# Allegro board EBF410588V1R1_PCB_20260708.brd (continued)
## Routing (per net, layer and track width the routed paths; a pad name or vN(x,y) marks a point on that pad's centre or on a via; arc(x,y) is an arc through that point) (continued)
HDMI_TX_D2N_PORT: length 21.8
  TOP w0.084: J33.3 98.59,80.48 arc(98.56,80.62) 98.48,80.74 98.41,80.81 arc(98.27,80.91) 98.1,80.94 98,80.94 arc(97.91,80.92) 97.84,80.88 97.69,80.72 arc(97.54,80.5) 97.49,80.23 97.49,78.89 arc(97.35,78.19) 96.95,77.6 94.2,74.84 arc(94.04,74.6) 93.98,74.32 93.98,68.65 arc(93.9,68.23) 93.66,67.88 93.1,67.32 arc(92.98,67.24) 92.84,67.21 92.48,67.21 arc(92.41,67.2) 92.36,67.16 91.91,66.71 arc(91.87,66.65) 91.86,66.58 91.86,66.34 arc(91.86,66.31) 91.88,66.28 91.96,66.2 arc(92.03,66.1) 92.05,65.97 D54.2 91.87,65.6 91.87,64.92 arc(91.88,64.86) 91.92,64.81 R229.1 91.85,64.16 arc(91.81,64.09) 91.79,64.01 91.79,63.99 arc(91.81,63.91) 91.85,63.84 C217.2
HDMI_TX_D2P: length 82
  TOP w0.084: CN2.69 65.92,45.48 arc(65.91,45.42) 65.88,45.37 65.87,45.36 arc(65.83,45.31) 65.82,45.25 65.82,44.28 arc(65.83,44.22) 65.87,44.17 v1(65.92,44.11) ; v1(91.22,59.43) 91.37,59.43 arc(91.41,59.44) 91.43,59.46 91.44,59.46 arc(91.55,59.63) 91.59,59.84 91.59,62.05 arc(91.59,62.08) 91.57,62.11 C216.1
  BOTTOM w0.084: v1(65.92,44.11) 65.92,43.92 arc(65.89,43.76) 65.8,43.63 65.53,43.35 arc(65.46,43.25) 65.43,43.12 65.43,42.97 65.44,42.96 65.44,42.8 arc(65.48,42.6) 65.59,42.43 66.06,41.96 arc(66.09,41.92) 66.1,41.87 66.1,40.55 arc(66.14,40.35) 66.25,40.17 67.38,39.05 arc(67.75,38.8) 68.18,38.71 74.21,38.71 arc(74.78,38.6) 75.26,38.28 75.45,38.09 arc(75.99,37.72) 76.63,37.6 97.28,37.6 arc(97.92,37.72) 98.46,38.09 105.09,44.71 arc(105.46,45.26) 105.58,45.9 105.58,53.87 arc(105.46,54.51) 105.09,55.06 104.59,55.55 arc(104.27,56.03) 104.16,56.6 104.16,56.99 arc(104.03,57.64) 103.67,58.18 103.53,58.32 arc(103.21,58.8) 103.09,59.37 103.09,59.69 arc(102.83,60.33) 102.18,60.6 99.06,60.6 arc(98.42,60.47) 97.88,60.11 97.77,60 arc(97.29,59.68) 96.72,59.56 93.68,59.56 arc(93.61,59.58) 93.54,59.62 93.14,60.02 arc(92.75,60.28) 92.29,60.38 91.97,60.38 arc(91.78,60.34) 91.63,60.23 91.61,60.22 arc(91.5,60.06) 91.47,59.87 91.47,59.84 arc(91.44,59.69) 91.35,59.56 v1(91.22,59.43)
HDMI_TX_D2P_PORT: length 21.8
  TOP w0.084: J33.1 98.41,81.29 arc(98.25,81.18) 98.05,81.14 98,81.14 arc(97.84,81.11) 97.7,81.02 97.55,80.86 arc(97.36,80.57) 97.29,80.23 97.29,78.89 arc(97.16,78.26) 96.81,77.74 94.06,74.98 arc(93.85,74.68) 93.78,74.32 93.78,68.65 arc(93.71,68.31) 93.52,68.02 92.96,67.46 arc(92.9,67.42) 92.84,67.41 92.48,67.41 arc(92.34,67.38) 92.22,67.3 91.77,66.85 arc(91.69,66.73) 91.66,66.58 91.66,66.34 arc(91.65,66.31) 91.63,66.28 91.55,66.2 arc(91.49,66.1) 91.46,65.97 D53.2 91.57,65.68 arc(91.64,65.57) 91.67,65.44 91.67,65.28 arc(91.62,65.03) 91.47,64.81 R230.1 91.53,64.17 arc(91.58,64.09) 91.59,64.01 91.59,63.99 arc(91.58,63.91) 91.53,63.83 C216.2
HDMI_TX_D3N: length 74.5
  TOP w0.084: v1(66.92,43.11) 66.92,43.3 arc(66.89,43.45) 66.8,43.59 66.63,43.75 arc(66.48,43.99) 66.42,44.26 66.42,45.25 arc(66.41,45.31) 66.38,45.36 66.37,45.37 arc(66.33,45.42) 66.32,45.48 CN2.71 ; v1(101.26,59.43) 101.38,59.43 arc(101.46,59.45) 101.53,59.49 101.54,59.5 arc(101.59,59.57) 101.6,59.65 101.6,60.1 arc(101.54,60.25) 101.39,60.31 101.22,60.31 arc(100.93,60.43) 100.81,60.72 100.81,60.73 arc(100.93,61.01) 101.21,61.13 101.39,61.13 arc(101.54,61.19) 101.6,61.34 101.6,61.94 arc(101.57,62.1) 101.48,62.23 C223.1
  BOTTOM w0.084: v1(101.26,59.43) 101.44,59.43 arc(101.55,59.41) 101.64,59.35 101.65,59.34 arc(101.71,59.25) 101.73,59.14 101.73,59.06 arc(101.71,58.94) 101.64,58.84 101.52,58.72 arc(101.37,58.5) 101.32,58.24 101.32,57.86 arc(101.44,57.57) 101.73,57.45 102.84,57.45 arc(103.05,57.24) 102.84,57.03 100.58,57.03 arc(100.23,56.88) 100.08,56.53 100.08,56.39 arc(100.19,56.12) 100.46,56.01 102.03,56.01 arc(102.24,55.8) 102.03,55.59 101.83,55.59 arc(101.47,55.44) 101.32,55.08 101.32,54.97 arc(101.45,54.67) 101.74,54.55 102.85,54.55 arc(103.42,54.43) 103.9,54.11 103.96,54.05 arc(104.28,53.57) 104.39,53.01 104.39,46.42 arc(104.28,45.85) 103.96,45.37 97.67,39.09 arc(97.2,38.77) 96.63,38.65 78.19,38.65 arc(77.62,38.77) 77.14,39.09 76.7,39.53 arc(76.15,39.9) 75.51,40.03 68.27,40.03 arc(68.02,40.07) 67.81,40.21 67.67,40.36 arc(67.64,40.42) 67.67,40.47 arc(67.69,40.53) 67.67,40.59 67.54,40.71 arc(67.49,40.73) 67.43,40.71 67.43,40.71 arc(67.37,40.69) 67.32,40.71 67.24,40.78 arc(67.16,40.91) 67.13,41.05 67.13,41.56 arc(67.15,41.62) 67.21,41.64 arc(67.26,41.66) 67.28,41.72 67.28,41.9 arc(67.26,41.95) 67.21,41.98 arc(67.15,42) 67.13,42.05 67.13,42.12 arc(67.11,42.25) 67.03,42.36 66.76,42.63 arc(66.7,42.73) 66.67,42.84 66.67,42.99 arc(66.71,43.08) 66.8,43.11 v1(66.92,43.11)
HDMI_TX_D3N_PORT: length 29.6
  TOP w0.084: C223.2 101.56,63.83 arc(101.61,63.91) 101.63,63.99 101.63,64.01 arc(101.61,64.09) 101.56,64.17 R227.1 101.46,64.76 arc(101.54,64.89) 101.57,65.05 101.57,65.44 arc(101.55,65.57) 101.48,65.68 D52.2 101.37,65.97 arc(101.39,66.1) 101.46,66.2 101.47,66.21 arc(101.54,66.31) 101.56,66.43 101.56,66.95 arc(101.61,67.18) 101.74,67.38 101.8,67.44 arc(102,67.57) 102.23,67.61 103.93,67.61 arc(104.08,67.64) 104.2,67.73 104.33,67.86 arc(104.42,67.98) 104.44,68.13 104.44,68.58 arc(104.33,68.86) 104.04,68.98 103.46,68.98 arc(103.05,69.39) 103.46,69.79 104.24,69.79 arc(104.44,70) 104.24,70.21 103.46,70.21 arc(103.05,70.62) 103.46,71.03 104.24,71.03 arc(104.38,71.09) 104.44,71.24 104.44,71.35 arc(104.36,71.57) 104.14,71.66 103.76,71.66 arc(103.35,72.06) 103.76,72.47 104.24,72.47 arc(104.44,72.68) 104.24,72.89 103.76,72.89 arc(103.35,73.3) 103.76,73.71 104.24,73.71 arc(104.44,73.92) 104.24,74.13 103.76,74.13 arc(103.35,74.53) 103.76,74.94 104.24,74.94 arc(104.38,75) 104.44,75.15 104.44,75.36 104.33,75.48 arc(104.2,75.56) 104.05,75.59 101.66,75.59 arc(101.6,75.57) 101.58,75.52 arc(101.56,75.46) 101.5,75.44 101.32,75.44 arc(101.27,75.46) 101.24,75.52 arc(101.22,75.57) 101.17,75.59 100.99,75.59 arc(100.93,75.57) 100.91,75.52 arc(100.89,75.46) 100.83,75.44 100.65,75.44 arc(100.6,75.46) 100.57,75.52 arc(100.55,75.57) 100.5,75.59 100.24,75.59 arc(100.08,75.56) 99.95,75.48 J33.12
HDMI_TX_D3P: length 74.5
  TOP w0.084: C222.1 101.92,62.18 arc(101.83,62.04) 101.8,61.89 101.8,61.34 arc(101.68,61.05) 101.39,60.93 101.21,60.93 arc(101.07,60.87) 101.01,60.73 101.01,60.72 arc(101.07,60.57) 101.22,60.51 101.39,60.51 arc(101.68,60.39) 101.8,60.1 101.8,59.94 arc(101.83,59.79) 101.92,59.66 v1(102.15,59.43) ; v1(66.92,44.11) 66.78,44.11 arc(66.67,44.16) 66.62,44.27 66.62,45.25 arc(66.63,45.31) 66.67,45.36 66.68,45.37 arc(66.71,45.42) 66.72,45.48 CN2.73
  BOTTOM w0.084: v1(66.92,44.11) 66.92,43.93 arc(66.89,43.77) 66.8,43.64 66.47,43.31 arc(66.41,43.15) 66.47,42.99 66.48,42.99 66.48,42.84 arc(66.51,42.65) 66.62,42.49 66.89,42.22 arc(66.92,42.18) 66.93,42.12 66.93,41.05 arc(66.98,40.83) 67.1,40.64 67.67,40.07 arc(67.95,39.89) 68.27,39.83 75.51,39.83 arc(76.08,39.71) 76.56,39.39 77,38.95 arc(77.55,38.58) 78.19,38.46 96.63,38.46 arc(97.27,38.58) 97.82,38.95 104.1,45.23 arc(104.46,45.78) 104.59,46.42 104.59,53.01 arc(104.46,53.65) 104.1,54.19 104.04,54.25 arc(103.5,54.62) 102.85,54.75 101.74,54.75 arc(101.59,54.81) 101.52,54.97 101.52,55.08 arc(101.61,55.3) 101.83,55.39 102.03,55.39 arc(102.44,55.8) 102.03,56.2 100.46,56.2 arc(100.33,56.26) 100.28,56.39 100.28,56.53 arc(100.37,56.74) 100.58,56.83 102.84,56.83 arc(103.25,57.24) 102.84,57.65 101.73,57.65 arc(101.58,57.71) 101.52,57.86 101.52,58.24 arc(101.56,58.43) 101.66,58.58 101.78,58.7 arc(101.89,58.87) 101.93,59.06 101.93,59.07 arc(101.95,59.2) 102.03,59.31 v1(102.15,59.43)
HDMI_TX_D3P_PORT: length 29.6
  TOP w0.084: C222.2 101.89,63.84 arc(101.84,63.91) 101.82,63.99 101.82,64.01 arc(101.84,64.09) 101.89,64.16 R228.1 101.89,64.87 arc(101.8,65) 101.77,65.15 101.77,65.47 arc(101.8,65.59) 101.86,65.69 D51.2 101.96,65.97 arc(101.94,66.1) 101.87,66.2 101.86,66.21 arc(101.79,66.31) 101.76,66.43 101.76,66.95 arc(101.79,67.1) 101.88,67.24 101.94,67.3 arc(102.08,67.39) 102.23,67.42 103.93,67.42 arc(104.15,67.46) 104.34,67.59 104.47,67.72 arc(104.6,67.91) 104.64,68.13 104.64,68.58 arc(104.47,69) 104.04,69.18 103.46,69.18 arc(103.25,69.39) 103.46,69.59 104.24,69.59 arc(104.64,70) 104.24,70.41 103.46,70.41 arc(103.25,70.62) 103.46,70.83 104.24,70.83 arc(104.52,70.95) 104.64,71.24 104.64,71.35 arc(104.5,71.71) 104.14,71.86 103.76,71.86 arc(103.55,72.06) 103.76,72.27 104.24,72.27 arc(104.64,72.68) 104.24,73.09 103.76,73.09 arc(103.55,73.3) 103.76,73.51 104.24,73.51 arc(104.64,73.92) 104.24,74.32 103.76,74.32 arc(103.55,74.53) 103.76,74.74 104.24,74.74 arc(104.52,74.86) 104.64,75.15 104.64,75.44 104.47,75.62 arc(104.28,75.75) 104.05,75.79 100.24,75.79 arc(100.08,75.82) 99.95,75.91 J33.10
HDMI_TX_EARC+: length 11.4
  TOP w0.084: J33.14 99.9,73.65 arc(100.12,73.31) 100.2,72.92 100.2,71.7 arc(100.15,71.42) 99.99,71.19 99.08,70.27 arc(99,70.15) 98.97,70.01 98.97,66.43 arc(98.99,66.31) 99.06,66.21 99.07,66.2 arc(99.14,66.1) 99.17,65.97 D44.2 99.06,65.68 arc(98.99,65.58) 98.97,65.46 98.97,64 arc(99,63.85) 99.09,63.72 C224.2
HDMI_TX_EARC-: length 10.7
  TOP w0.084: J33.19 98.59,71.13 98.73,71.27 arc(98.92,71.35) 99.11,71.27 99.33,71.05 arc(99.38,70.93) 99.33,70.81 98.94,70.41 arc(98.81,70.23) 98.77,70.01 98.77,69.46 arc(98.75,69.4) 98.7,69.38 arc(98.65,69.36) 98.63,69.31 98.63,69.12 arc(98.65,69.07) 98.7,69.05 arc(98.75,69.03) 98.77,68.98 98.77,68.78 arc(98.75,68.73) 98.7,68.71 arc(98.65,68.69) 98.63,68.64 98.63,68.45 arc(98.65,68.4) 98.7,68.38 arc(98.75,68.36) 98.77,68.31 98.77,68.11 arc(98.75,68.06) 98.7,68.04 arc(98.65,68.02) 98.63,67.97 98.63,67.78 arc(98.65,67.73) 98.7,67.71 arc(98.75,67.69) 98.77,67.64 98.77,67.44 arc(98.75,67.39) 98.7,67.37 arc(98.65,67.35) 98.63,67.3 98.63,67.11 arc(98.65,67.06) 98.7,67.04 arc(98.75,67.02) 98.77,66.97 98.77,66.43 arc(98.75,66.31) 98.68,66.21 98.67,66.2 arc(98.6,66.1) 98.57,65.97 D31.2 98.68,65.68 arc(98.75,65.58) 98.77,65.46 98.77,64.29 arc(98.71,63.99) 98.54,63.73 C225.2 R149.2
HDMI_TX_HPDIN_M0: length 25.8
  TOP w0.152: CN3.54 86.32,50.36 86.52,50.56 v1(86.52,50.79) ; v1(97.54,57.61) 98.01,58.08 Q8.3 100.98,58.08 101.21,57.85 101.21,55.42 101.76,54.86 R141.2
  BOTTOM w0.152: v1(86.52,50.79) 86.57,50.79 87.02,51.23 87.02,52.1 87.33,52.4 94.11,52.4 94.89,53.19 94.89,55.52 96.98,57.61 v1(97.54,57.61)
HDMI_TX_ON_H: length 14.3
  TOP w0.152: CN3.52 85.92,50.5 86.01,50.59 86.01,51.27 v1(86.52,51.79) ; R164.1 v1(94.34,54.86)
  BOTTOM w0.152: v1(94.34,54.86) 94.34,53.42 93.75,52.83 87.07,52.83 86.52,52.28 v1(86.52,51.79)
HDMI_TX_SBDN: length 94.7
  TOP w0.084: v1(67.92,43.11) 67.92,43.29 arc(67.89,43.44) 67.81,43.57 67.57,43.81 arc(67.49,43.93) 67.46,44.07 67.46,44.5 arc(67.44,44.62) 67.37,44.72 67.36,44.72 arc(67.26,44.88) 67.22,45.07 67.22,45.25 arc(67.21,45.31) 67.18,45.36 67.17,45.37 arc(67.13,45.42) 67.12,45.48 CN2.75 ; v1(98.34,59.43) 98.42,59.43 arc(98.49,59.44) 98.55,59.48 98.61,59.54 arc(98.68,59.65) 98.71,59.78 98.71,61.92 arc(98.68,62.07) 98.59,62.2 C225.1
  BOTTOM w0.084: v1(98.34,59.43) 98.54,59.22 arc(98.65,59.07) 98.68,58.88 98.68,58.88 arc(98.8,58.59) 99.09,58.47 99.62,58.47 arc(99.83,58.26) 99.62,58.05 99.09,58.05 arc(98.8,57.93) 98.68,57.64 98.68,55.46 arc(98.8,55.17) 99.09,55.05 99.8,55.05 arc(100,54.84) 99.8,54.63 99.19,54.63 arc(98.83,54.48) 98.68,54.13 98.68,54.01 arc(98.8,53.72) 99.09,53.61 102.82,53.61 arc(103.03,53.4) 102.82,53.19 99.09,53.19 arc(98.68,52.78) 99.09,52.37 103.25,52.37 arc(103.46,52.16) 103.25,51.95 99.09,51.95 arc(98.8,51.83) 98.68,51.54 98.68,51.45 arc(98.72,51.27) 98.82,51.11 98.84,51.1 arc(98.99,50.99) 99.18,50.96 103.22,50.96 arc(103.37,50.9) 103.43,50.75 103.43,46.43 arc(103.4,46.29) 103.32,46.17 100.46,43.31 arc(100.31,43.25) 100.16,43.31 99.88,43.6 arc(99.3,43.6) 99.3,43.02 99.59,42.73 arc(99.65,42.59) 99.59,42.44 99.59,42.44 arc(99.44,42.38) 99.29,42.44 99,42.72 arc(98.43,42.72) 98.43,42.15 98.71,41.86 arc(98.77,41.71) 98.71,41.56 arc(98.56,41.5) 98.42,41.56 98.13,41.85 arc(97.55,41.85) 97.55,41.27 97.84,40.99 arc(97.9,40.84) 97.84,40.69 97.84,40.69 arc(97.69,40.63) 97.54,40.69 97.26,40.98 arc(96.68,40.98) 96.68,40.4 96.91,40.17 arc(97,39.96) 96.91,39.76 96.9,39.75 arc(96.68,39.6) 96.41,39.55 78.05,39.55 arc(77.91,39.58) 77.8,39.65 76.64,40.81 arc(76.33,41.02) 75.96,41.09 75.64,41.09 arc(75.58,41.12) 75.56,41.17 arc(75.54,41.23) 75.48,41.25 75.3,41.25 arc(75.25,41.23) 75.22,41.17 arc(75.2,41.12) 75.15,41.09 74.97,41.09 arc(74.91,41.12) 74.89,41.17 arc(74.87,41.23) 74.81,41.25 74.63,41.25 arc(74.58,41.23) 74.55,41.17 arc(74.53,41.12) 74.48,41.09 74.3,41.09 arc(74.24,41.12) 74.22,41.17 arc(74.2,41.23) 74.14,41.25 73.96,41.25 arc(73.91,41.23) 73.88,41.17 arc(73.86,41.12) 73.8,41.09 73.63,41.09 arc(73.57,41.12) 73.55,41.17 arc(73.53,41.23) 73.47,41.25 73.29,41.25 arc(73.24,41.23) 73.21,41.17 arc(73.19,41.12) 73.13,41.09 72.96,41.09 arc(72.9,41.12) 72.88,41.17 arc(72.85,41.23) 72.8,41.25 72.62,41.25 arc(72.57,41.23) 72.54,41.17 arc(72.52,41.12) 72.46,41.09 72.29,41.09 arc(72.23,41.12) 72.21,41.17 arc(72.18,41.23) 72.13,41.25 71.95,41.25 arc(71.89,41.23) 71.87,41.17 arc(71.85,41.12) 71.79,41.09 71.62,41.09 arc(71.56,41.12) 71.54,41.17 arc(71.51,41.23) 71.46,41.25 71.28,41.25 arc(71.22,41.23) 71.2,41.17 arc(71.18,41.12) 71.12,41.09 70.94,41.09 arc(70.89,41.12) 70.87,41.17 arc(70.84,41.23) 70.79,41.25 70.61,41.25 arc(70.55,41.23) 70.53,41.17 arc(70.51,41.12) 70.45,41.09 70.27,41.09 arc(70.22,41.12) 70.2,41.17 arc(70.17,41.23) 70.12,41.25 69.94,41.25 arc(69.88,41.23) 69.86,41.17 arc(69.84,41.12) 69.78,41.09 69.6,41.09 arc(69.55,41.12) 69.52,41.17 arc(69.5,41.23) 69.45,41.25 69.27,41.25 arc(69.21,41.23) 69.19,41.17 arc(69.17,41.12) 69.11,41.09 68.93,41.09 arc(68.88,41.12) 68.85,41.17 arc(68.83,41.23) 68.78,41.25 68.6,41.25 arc(68.54,41.23) 68.52,41.17 arc(68.5,41.12) 68.44,41.09 68.23,41.09 arc(68.06,41.16) 68,41.33 68,41.57 arc(68.02,41.62) 68.07,41.64 arc(68.13,41.67) 68.15,41.72 68.15,41.9 arc(68.13,41.96) 68.07,41.98 arc(68.02,42) 68,42.05 68,42.13 arc(67.97,42.26) 67.9,42.36 67.75,42.51 arc(67.67,42.63) 67.64,42.78 67.64,42.96 arc(67.68,43.07) 67.79,43.11 v1(67.92,43.11)
HDMI_TX_SBDP: length 93.1
  TOP w0.084: v1(99.22,59.43) 99.02,59.63 arc(98.94,59.76) 98.91,59.92 98.91,61.92 arc(98.94,62.07) 99.02,62.2 C224.1 ; CN2.77 67.52,45.48 arc(67.51,45.42) 67.48,45.37 67.47,45.36 arc(67.43,45.31) 67.42,45.25 67.42,45.07 arc(67.44,44.96) 67.51,44.86 67.55,44.82 arc(67.64,44.69) 67.67,44.54 67.67,44.25 arc(67.71,44.15) 67.8,44.11 v1(67.92,44.11)
  BOTTOM w0.084: v1(99.22,59.43) 99.02,59.23 arc(98.92,59.07) 98.88,58.89 98.88,58.88 arc(98.94,58.73) 99.09,58.67 99.62,58.67 arc(100.03,58.26) 99.62,57.85 99.09,57.85 arc(98.94,57.79) 98.88,57.64 98.88,55.46 arc(98.94,55.31) 99.09,55.25 99.8,55.25 arc(100.2,54.84) 99.8,54.43 99.19,54.43 arc(98.97,54.34) 98.88,54.13 98.88,54.01 arc(98.94,53.86) 99.09,53.8 102.82,53.8 arc(103.23,53.4) 102.82,52.99 99.09,52.99 arc(98.88,52.78) 99.09,52.57 103.25,52.57 arc(103.66,52.16) 103.25,51.75 99.09,51.75 arc(98.94,51.69) 98.88,51.54 98.88,51.45 arc(98.9,51.34) 98.96,51.25 98.98,51.24 arc(99.07,51.18) 99.18,51.16 103.22,51.16 arc(103.51,51.04) 103.63,50.75 103.63,46.43 arc(103.58,46.22) 103.46,46.03 100.6,43.17 arc(100.31,43.05) 100.02,43.17 99.74,43.46 arc(99.44,43.46) 99.44,43.16 99.73,42.87 arc(99.85,42.59) 99.73,42.3 99.73,42.3 arc(99.44,42.18) 99.15,42.3 98.86,42.58 arc(98.57,42.58) 98.57,42.29 98.85,42 arc(98.97,41.71) 98.85,41.42 98.85,41.42 arc(98.56,41.3) 98.28,41.42 97.99,41.71 arc(97.69,41.71) 97.69,41.41 97.98,41.13 arc(98.1,40.84) 97.98,40.55 97.98,40.55 arc(97.69,40.43) 97.4,40.55 97.12,40.84 arc(96.82,40.84) 96.82,40.54 97.05,40.31 arc(97.19,39.96) 97.05,39.62 97.04,39.61 arc(96.75,39.42) 96.41,39.35 78.05,39.35 arc(77.84,39.39) 77.66,39.51 76.5,40.67 arc(76.25,40.84) 75.96,40.89 68.23,40.89 arc(67.92,41.02) 67.8,41.33 67.8,42.13 arc(67.79,42.18) 67.76,42.22 67.61,42.37 arc(67.49,42.56) 67.44,42.78 67.44,42.96 67.44,42.97 arc(67.37,43.12) 67.44,43.28 67.81,43.65 arc(67.89,43.78) 67.92,43.93 v1(67.92,44.11)
HDMI_TX_SCL: length 17.8
  TOP w0.152: CN3.50 v1(85.52,50.79)
  BOTTOM w0.152: v1(85.52,50.79) 85.04,51.27 85.04,53.39 86.09,54.44 86.09,56.81 88.11,58.83 88.11,62.83 R139.2 88.71,63.43 Q6.2
HDMI_TX_SCL_PORT: length 16.6
  BOTTOM w0.152: R140.2 91.14,66.84 Q6.3 89.66,67.97 90.5,68.81 92.48,68.81 94.08,70.41 94.08,72.64 94.74,73.3 95.8,73.3 96.16,73.66 D45.2 98.18,73.79 J33.15
HDMI_TX_SDA: length 33.1
  TOP w0.152: CN3.48 85.12,50.49 85.01,50.6 85.01,51.27 v1(85.52,51.79)
  BOTTOM w0.152: v1(85.52,51.79) 85.52,53.16 86.56,54.2 86.56,56.57 88.57,58.57 88.57,61.24 90.03,62.7 94.48,62.7 94.95,63.17 99.06,63.17 100.1,64.21 101.07,64.21 Q7.2 102.35,64.12 104.5,64.12 R146.2
HDMI_TX_SDA_PORT: length 10.4
  BOTTOM w0.152: J33.16 100.37,72.8 102.89,70.29 D46.2 102.89,67.84 102.62,67.56 Q7.3 101.97,66.84 101.4,66.27 100.69,66.27 R147.2
HP_BUTTON_DET: length 76.5
  TOP w0.152: v1(91.52,50.79) 91.43,50.79 90.32,49.68 CN3.74
  ART03 w0.203: v1(91.52,50.79) 92.05,51.31 92.05,52.93 90.35,54.64 90.35,57.76 89.33,58.78 89.33,63.7 87.88,65.15 87.88,69.29 87,70.18 50.22,70.18 49.89,70.51 48.95,70.51 48.39,71.07 44.37,71.07 43.76,70.46 42.85,70.46 42.34,70.97 42.34,73.46 v1(43.18,74.3)
  BOTTOM w0.203: v1(43.18,74.3) 43.19,74.29 R86.1 ; R86.1 43.95,74.3 R83.2 ; R86.1 C77.1
HP_PLUG_IN_DET: length 62
  TOP w0.152: CN3.76 90.72,49.57 91.26,50.11 91.57,50.11 92.01,50.55 92.01,51.27 92.53,51.79 v1(92.56,51.79)
  TOP w0.203: v1(52.43,70.71) 52.08,70.37 R88.2
  ART03 w0.203: v1(92.56,51.79) 92.56,54.28 91,55.84 91,58.13 89.71,59.41 89.71,64.29 89.15,64.85 89.15,69.57 88.01,70.71 v1(52.43,70.71)
I2C2_SCL_M0: length 165.9
  TOP w0.152: v1(29.87,46.38) 30.48,46.99 33.12,46.99 34.04,46.08 37.77,46.08 41.22,42.62 54.14,42.62 54.44,42.93 54.44,43.65 54.91,44.11 v1(54.92,44.11) 55.12,44.31 CN2.15 ; v1(38.69,64.44) 38.69,64.2 37.11,62.61 37.11,52.81 35.22,50.92 30.9,50.92 30.38,50.39 29.39,50.39 v1(28.87,50.92) ; J13.9 140.45,16.55 137.83,19.17 v1(137.83,19.56)
  ART03 w0.152: v1(137.83,19.56) 136.02,21.36 131.9,21.36 129.64,23.62 123.77,23.62 123.19,24.21 98.07,24.21 97.01,25.26 97.01,30.42 97.5,30.91 v1(97.5,31.08) ; v1(29.87,46.38) 29.49,46.76 29.49,50.3 v1(28.87,50.92)
  BOTTOM w0.152: R239.2 54.43,42.38 54.43,43.64 54.91,44.11 v1(54.92,44.11) 55.41,43.63 55.41,40.78 58.54,37.65 61.47,37.65 66.36,32.77 95.81,32.77 v1(97.5,31.08) ; U11.6 v1(38.69,64.44)
I2C2_SDA_M0: length 159.5
  TOP w0.152: v1(37.64,64.44) 37.64,63.7 36.77,62.83 36.77,53.02 35.15,51.41 30.63,51.41 v1(30.14,50.92) ; v1(30.87,46.38) 32.94,46.38 33.78,45.54 37.62,45.54 40.92,42.24 54.36,42.24 54.92,42.81 v1(54.92,43.11) 55.44,43.63 55.44,44.31 55.52,44.4 CN2.17 ; v1(137.74,20.52) 138.83,19.44 138.83,18.96 140.74,17.05 J13.10
  ART03 w0.152: v1(30.14,50.92) 30.14,47.74 30.87,47.01 v1(30.87,46.38) ; v1(137.74,20.52) 137.74,21.08 136.88,21.95 134.09,21.95 133.65,22.38 131.88,22.38 129.57,24.69 98.55,24.69 97.97,25.27 97.97,29.43 97.5,29.91 v1(97.5,30.03)
  BOTTOM w0.152: v1(37.64,64.44) 37.98,64.44 38.19,64.65 U11.7 ; v1(97.5,30.03) 97.5,30.08 95.17,32.41 66.01,32.41 61.18,37.24 58.12,37.24 R240.2 54.92,41.85 v1(54.92,43.11)
I2C3_SCL_M0: length 166.1
  TOP w0.152: U9.28 46.78,65.41 46.41,65.79 45.48,65.79 v1(45.11,65.41) 44.64,65.89 43.31,65.89 42.49,65.07 37.54,65.07 37.16,64.69 37.16,63.78 36.42,63.04 36.42,53.26 35.08,51.92 v1(30.14,51.92) ; J14.6 v1(7.67,14.85) ; v1(83.22,13.02) 83.12,12.92 CN5.38
  ART03 w0.152: v1(45.11,65.41) 46.15,64.37 46.15,62.05 48.39,59.82 48.39,58.75 49.38,57.76 49.38,27.13 46.41,24.16 46.41,22.14 v1(44.31,20.05)
  BOTTOM w0.152: v1(30.14,51.92) 30.87,52.65 U5.6 ; v1(83.22,13.02) 82.64,12.45 81.1,12.45 80.71,12.84 80.71,13.3 79.15,14.86 R162.2 75.61,15.42 74.09,15.42 73.03,16.48 65.66,16.48 62.03,20.12 44.38,20.12 v1(44.31,20.05) 44.12,20.24 14.58,20.24 13.67,19.33 13.67,17.17 13.28,16.79 12.4,16.79 12.06,16.46 10.69,16.46 10.41,16.18 10.41,15.7 10.05,15.33 8.15,15.33 v1(7.67,14.85)
I2C3_SDA_M0: length 171.5
  TOP w0.152: J14.5 8.17,14.35 v1(8.67,14.85) ; v1(30.14,52.92) 30.61,52.45 34.96,52.45 36.09,53.58 36.09,63.35 36.78,64.03 36.78,64.85 37.47,65.53 42.19,65.53 43.64,66.98 44.54,66.98 v1(45.11,66.41) 46.36,66.41 47.23,65.54 U9.27 ; CN5.36 v1(82.72,11.18)
  ART03 w0.152: v1(45.11,66.41) 46.74,64.79 46.74,62.41 49.38,59.77 49.38,58.72 50.42,57.68 50.42,53.8 49.83,53.21 49.83,26.74 46.91,23.83 46.91,21.65 v1(44.31,19.05)
  BOTTOM w0.152: v1(82.72,11.18) 81.99,11.91 80.54,11.91 79.74,12.72 79.74,13.4 79.3,13.84 R160.2 75.61,13.28 74.09,13.28 73.66,13.72 73.66,15.11 72.72,16.05 65.41,16.05 61.75,19.71 44.97,19.71 v1(44.31,19.05) 43.55,19.81 14.96,19.81 14.17,19.02 14.17,16.76 13,15.6 11.71,15.6 11.38,15.27 11.38,14.81 11.05,14.48 9.04,14.48 v1(8.67,14.85) ; U5.5 30.52,53.3 v1(30.14,52.92)
I2C4_SCL_M2: length 108.6
  TOP w0.152: v1(13.4,24.78) 12.39,23.77 10.74,23.77 5.55,28.97 5.55,30.78 5.03,31.29 5.03,33.55 5.53,34.05 J15.6 ; CN5.80 91.52,11.38 v1(91.72,11.18)
  BOTTOM w0.152: v1(91.72,11.18) 91.72,11.2 92.2,11.68 92.72,11.68 R188.2 92.85,12.32 91.47,12.32 91.16,12.62 91.16,14.96 89.33,16.79 86.58,16.79 84.94,18.43 84.94,21.23 81.58,24.59 65.94,24.59 65.38,25.15 52.58,25.15 51.77,25.96 16,25.96 14.82,24.78 v1(13.4,24.78)
I2C4_SDA_M2: length 105.7
  TOP w0.152: CN5.78 91.12,12.81 91.34,13.02 v1(92.22,13.02) ; J15.5 5.77,33.55 5.46,33.25 5.46,31.5 5.99,30.96 5.99,29.18 10.92,24.26 11.6,24.26 v1(12.13,24.78)
  BOTTOM w0.152: R163.2 93.04,13.02 v1(92.22,13.02) 92.22,14.03 91.62,14.63 91.62,15.16 89.56,17.22 86.76,17.22 85.39,18.59 85.39,21.62 82.07,24.94 66.14,24.94 65.53,25.55 52.88,25.55 52.04,26.39 15.67,26.39 14.61,25.32 12.67,25.32 v1(12.13,24.78)
I2C5_SCL_M3: length 120.5
  TOP w0.152: v1(93.72,18.51) 93.21,17.99 92.51,17.99 92.21,17.68 92.21,16.03 91.52,15.35 CN5.79
  ART03 w0.152: v1(31.91,31.75) 32.41,31.25 32.41,23.12 v1(32.56,22.97)
  BOTTOM w0.152: v1(31.91,31.75) 32.42,32.26 34.19,32.26 34.85,31.6 36.7,31.6 37.85,32.74 40.01,32.74 42.34,35.08 62.78,35.08 65.86,32 91.01,32 92.89,30.12 92.89,20.17 93.24,19.82 93.24,18.99 v1(93.72,18.51) 94.46,18.51 R190.2 ; v1(32.56,22.97) 32.03,23.5 24.94,23.5 24.13,22.68 22.99,22.68 22.2,23.47 12.09,23.47 9.97,21.35 J16.6
I2C5_SDA_M3: length 122.7
  TOP w0.152: CN5.77 91.12,15.51 91.72,16.11 91.72,18.2 92.03,18.51 v1(92.72,18.51)
  ART03 w0.152: v1(33.56,22.97) 33.54,22.97 33.05,22.48 32.21,22.48 31.91,22.78 v1(31.91,30.75)
  BOTTOM w0.152: v1(31.91,30.75) 31.91,30.27 32.49,29.69 34.92,29.69 35.59,30.35 40.44,30.35 41.17,31.09 41.17,32.08 43.21,34.11 62.38,34.11 65.33,31.17 90.14,31.17 91.89,29.42 91.89,19.34 v1(92.72,18.51) 92.75,18.51 93.24,18.01 94.98,18.01 R189.2 ; J16.5 9.91,21.85 11.94,23.88 22.37,23.88 23.16,23.09 23.96,23.09 24.85,23.98 32.55,23.98 v1(33.56,22.97)
I2C7_SCL_M1: length 221.5
  TOP w0.152: v1(110.85,33.3) 110.92,33.38 110.92,46.02 112.45,47.55 123.44,47.55 123.9,48.01 140.41,48.01 143.13,50.72 143.13,57.63 J32.5 ; CN5.42 83.92,12.72 v1(84.22,13.02) ; J18.6 5.12,52.87 3.63,51.38 2.87,51.38 2.86,51.38 2.09,50.6 2.09,28.49 3.15,27.43 5.71,27.43 10.19,22.96 12.66,22.96 v1(13.4,22.23)
  ART03 w0.152: v1(84.22,13.02) 84.22,13.33 84.89,14 89.15,14 91.67,16.51 91.67,33.5 94.69,36.53 107.62,36.53 v1(110.85,33.3)
  BOTTOM w0.152: v1(13.4,22.23) 13.4,21.78 14.2,20.98 62.53,20.98 65.91,17.6 75.66,17.6 R236.2 78.46,17.07 81.58,13.94 83.54,13.94 84.22,13.26 v1(84.22,13.02)
I2C7_SDA_M1: length 226
  TOP w0.152: CN5.40 83.52,11.38 v1(83.72,11.18) ; J32.3 142.6,59.64 142.6,51.08 139.93,48.41 123.55,48.41 123.06,47.93 112.09,47.93 110.51,46.35 110.51,33.97 v1(109.85,33.3) ; v1(13.4,20.95) 13.4,21.42 13.89,21.92 13.89,22.5 13.03,23.37 10.46,23.37 5.94,27.89 3.4,27.89 2.54,28.75 2.54,50.42 3.05,50.93 3.81,50.93 5.25,52.37 J18.5
  ART03 w0.152: v1(109.85,33.3) 109.85,33.66 107.47,36.04 94.82,36.04 92.1,33.32 92.1,16.33 89.33,13.56 85.08,13.56 84.74,13.22 84.74,12.19 v1(83.72,11.18)
  BOTTOM w0.152: v1(83.72,11.18) 83.72,13.21 83.42,13.51 81.18,13.51 78.74,15.95 R235.2 75.66,16.48 74.17,16.48 73.69,16.97 65.86,16.97 62.26,20.57 13.78,20.57 v1(13.4,20.95)
I2C8_SCL_M2: length 138.3
  TOP w0.152: v1(16.24,48.56) 17.92,46.89 21.13,46.89 23.31,44.7 27.86,44.7 28.6,45.44 32.23,45.44 33.12,44.55 37.11,44.55 38.3,43.36 v1(38.3,42.23) ; CN5.76 v1(90.72,11.18)
  ART03 w0.152: v1(34.56,22.97) 35.07,22.45 35.77,22.45 36.07,22.76 36.07,23.35 37.11,24.38 39.9,24.38 42.48,26.96 42.48,40.09 40.94,41.63 38.9,41.63 v1(38.3,42.23)
  BOTTOM w0.152: J17.6 10.02,40.55 11.85,42.38 11.85,46.22 12.22,46.58 12.22,47.32 12.9,48.01 15.68,48.01 v1(16.24,48.56) ; v1(34.56,22.97) 37.16,25.57 51.47,25.57 52.33,24.71 65.21,24.71 66.29,23.62 R238.2 70.19,24.21 81.15,24.21 84.4,20.95 84.4,18.39 86.39,16.4 88.98,16.4 90.72,14.66 v1(90.72,11.18)
I2C8_SDA_M2: length 132.1
  TOP w0.152: CN5.74 90.32,12.92 v1(90.22,13.02) ; v1(37.3,42.23) 37.3,43.47 36.63,44.15 23.11,44.15 20.9,46.35 17.45,46.35 v1(15.24,48.56)
  ART03 w0.152: v1(37.3,42.23) 38.41,41.12 40.72,41.12 42.03,39.81 42.03,27.19 39.67,24.84 36.91,24.84 35.56,23.49 v1(35.56,22.97)
  BOTTOM w0.152: v1(90.22,13.02) 90.22,14.45 88.65,16.03 86.21,16.03 84,18.24 84,20.55 80.72,23.83 72.84,23.83 R237.2 72.64,23.11 71.88,22.35 66.93,22.35 65.05,24.23 52.04,24.23 51.18,25.1 37.68,25.1 v1(35.56,22.97) ; v1(15.24,48.56) 12.8,48.56 11.77,47.53 11.77,46.77 11.4,46.4 11.4,42.57 9.88,41.05 J17.5
LCD_BL_PWM: length 136.8
  TOP w0.152: v1(141.39,19.05) 141.89,18.55 J13.13 ; v1(95.5,30.03) 95.5,30.54 95.16,30.87 56.47,30.87 54.18,28.57 52.56,28.57 52.18,28.19 52.18,27.51 v1(51.67,26.99) ; CN2.10 53.92,49.91 53.41,50.43 53.41,51.32 52.94,51.79 v1(52.92,51.79)
  ART03 w0.152: v1(95.5,30.03) 95.5,29.91 95,29.4 95,22.35 98.22,19.13 108.99,19.13 110.06,20.19 122.94,20.19 123.77,21.03 129.67,21.03 131.75,18.95 136.04,18.95 137.41,17.58 139.92,17.58 v1(141.39,19.05) ; v1(51.67,26.99) 50.83,27.83 50.83,47.98 52.5,49.66 52.5,51.36 v1(52.92,51.79)
LCD_PWR_EN: length 86.3
  TOP w0.152: CN2.45 61.12,44.31 v1(60.92,44.11)
  ART03 w0.152: v1(111.53,18.28) 111.53,17.37 110.92,16.76 110.03,16.76 109.65,17.14 96.9,17.14 93.01,21.03 93.01,32.31 93.52,32.82 93.52,33.99 94.08,34.54 v1(97.5,34.54)
  BOTTOM w0.152: R153.1 v1(111.53,18.28) ; v1(60.92,44.11) 61.85,43.19 61.85,39.76 67.07,34.54 v1(97.5,34.54)
LCD_RST: length 131.7
  TOP w0.152: v1(94.5,29.08) 94.01,29.57 57.43,29.57 54.33,26.47 53.19,26.47 v1(52.67,26.99) ; CN2.12 54.32,50.02 53.92,50.42 v1(53.92,50.79) ; v1(142.39,19.05) 142.39,19.24 142.7,19.55 J13.15
  ART03 w0.152: v1(52.67,26.99) 52.18,27.47 52.18,28.85 51.87,29.16 51.87,47.42 53.92,49.48 v1(53.92,50.79) ; v1(142.39,19.05) 141.81,18.46 141.81,17.63 141.58,17.4 140.75,17.4 140.31,16.97 137.19,16.97 135.84,18.31 131.65,18.31 129.95,20.02 123.8,20.02 123.34,19.56 110.19,19.56 109.27,18.64 97.94,18.64 94.5,22.09 v1(94.5,29.08)
LOUT1: length 6.8
  TOP w0.203: v1(48.85,59.69) 48.58,59.96 U9.12
  BOTTOM w0.203: v1(48.85,59.69) 48.51,60.03 48.51,60.71 49,61.19 49,62.89 C81.2
LOUT2: length 41.3
  TOP w0.203: v1(51.13,61.29) 50.91,61.51 U9.15 ; v1(35.88,64.66) 35.88,64.48 35.03,63.63 35.03,54.66 34.1,53.74 28.06,53.74 C86.1
  BOTTOM w0.203: v1(51.13,61.29) 50.29,61.29 50.01,61.01 50.01,60.3 50.37,59.94 50.37,59.28 49.89,58.8 45.57,58.8 43.23,61.14 43.23,62.33 42.75,62.81 41.56,62.81 40.72,63.65 36.89,63.65 v1(35.88,64.66)
MASKROM: length 18.4
  BOTTOM w0.152: SW1.2 144.42,81.58 142.93,80.09 142.93,75.23 141.13,73.44 D11.2 140.28,71.37 139.65,72.01 138.29,72.01 137.66,71.38 C25.1 137.58,71.37 137.05,71.9 135.78,71.9 R27.1
MIC1N: length 1.4
  TOP w0.203: C74.2 R85.2
MIC1P: length 1.4
  TOP w0.203: R81.2 C71.2
MIC2N: length 31.7
  TOP w0.203: C76.2 v1(52.42,68.95)
  ART03 w0.203: v1(39.61,81.53) 39.26,81.19 39.26,80.42 39.67,80.01 40.86,80.01 41.48,79.4 41.48,70.76 42.46,69.77 48.13,69.77 49.11,68.8 52.27,68.8 v1(52.42,68.95)
  BOTTOM w0.203: C89.2 40.63,82.8 R101.1 ; C89.2 39.27,83.15 39.27,85.64 P1.2 ; C89.2 39.29,82.48 39.29,81.85 v1(39.61,81.53)
MIC2P: length 36
  TOP w0.203: v1(53.42,68.95) 52.85,69.52 50.6,69.52 C75.2
  ART03 w0.203: v1(38.61,81.53) 38.91,81.24 38.91,80.27 39.52,79.65 40.72,79.65 41.12,79.25 41.12,70.61 42.34,69.39 47.96,69.39 48.9,68.44 52.63,68.44 53.14,68.95 v1(53.42,68.95)
  BOTTOM w0.203: v1(38.61,81.53) 38.94,81.86 38.94,82.48 C89.1 ; C89.1 37.6,82.8 R99.2 ; C89.1 38.91,83.1 38.91,85.19 P1.1
MINIPCIE_3V3: length 31.1
  TOP w0.254: C174.1 v1(132.51,8.5)
  TOP w0.381: v1(111.79,21.69) 112.3,21.69 C175.1 112.99,21.01 J20.2 ; v1(125.09,24.16) 125.76,23.5 125.76,21.97 125.26,21.47 C172.1 124.99,21.36 J20.24 ; v1(136.59,21.47) C173.1 135.89,20.83 136.19,20.53 J20.52
  ART04 w0.254: v1(108.03,28.44) 108.03,27.78 108.58,27.23 110.82,27.23 112.75,25.3 119.84,25.3 120.32,24.82 120.32,23.67
  BOTTOM w0.254: v1(108.03,28.44) R172.2 C164.2 ; R179.1 113.16,7.7 v1(113.08,7.62)
  vias: v1(119.71,21.66) v1(119.71,20.66) v1(120.71,21.66) v1(120.71,20.66) v1(121.71,21.66) v1(121.71,20.66) v1(133.51,8.5)
MINIPCIE_NWDISABLE: length 113.5
  TOP w0.152: CN2.20 v1(55.92,50.79) ; v1(108.37,19.68) 108.37,17.31 108.92,16.76 112.06,16.76 113.14,15.69 119.52,15.69 120.68,16.84 120.68,18.85 121.19,19.36 121.19,21.88 121.79,22.47 R182.2 ; v1(95.5,29.08) 94.98,29.6 94.98,30.23 94.68,30.53 56.9,30.53 54.36,27.99 v1(53.67,27.99)
  ART03 w0.152: v1(108.37,19.68) 107.95,20.09 98.17,20.09 95.5,22.77 v1(95.5,29.08) ; v1(53.67,27.99) 53.67,29.49 53.44,29.72 53.44,45.87 54,46.43 54,47.02 55.92,48.94 v1(55.92,50.79)
MINIPCIE_PWR_EN: length 115.7
  TOP w0.152: CN2.22 56.32,50.5 56.41,50.59 56.41,51.3 v1(55.92,51.79)
  ART03 w0.152: v1(55.92,51.79) 55.92,51.78 55.41,51.27 55.41,49.31 53.42,47.32 53.42,46.56 52.91,46.05 52.91,29.49 53.18,29.21 53.18,27.47 v1(53.67,26.99) ; v1(92.72,14.51) 93.5,14.51 95.71,16.71 106.57,16.71 v1(107.16,16.12)
  BOTTOM w0.152: v1(92.72,14.51) 92.72,14.8 89.94,17.58 86.94,17.58 85.78,18.75 85.78,22.05 82.5,25.32 66.34,25.32 65.68,25.98 54.64,25.98 53.67,26.95 v1(53.67,26.99) ; R177.1 113.16,29.41 112.8,29.77 105.26,29.77 104.55,29.06 104.55,18.73 v1(107.16,16.12)
MIPI_DPHY_CSI0_RX_CLKN: length 99.9
  TOP w0.084: CN3.11 77.92,45.48 arc(77.93,45.42) 77.97,45.37 77.98,45.36 arc(78.01,45.31) 78.02,45.25 78.02,44.07 arc(77.91,43.5) 77.59,43.02 73.27,38.71 arc(72.79,38.39) 72.23,38.27 34.65,38.27 arc(34.17,38.18) 33.77,37.91 33.7,37.84 arc(33.36,37.62) 32.96,37.54 32.84,37.54 arc(32.34,37.44) 31.92,37.15 31.79,37.03 arc(31.37,36.74) 30.87,36.64 29.38,36.64 arc(29.3,36.66) 29.23,36.71 29.21,36.73 arc(29.17,36.79) 29.16,36.85 29.16,36.95 v1(29.2,36.99) ; J14.10 7.26,16.85 arc(7.35,16.83) 7.42,16.78 7.43,16.77 arc(7.51,16.72) 7.6,16.7 9.59,16.7 arc(9.76,16.77) 9.83,16.94 v1(9.83,17)
  ART03 w0.076: v1(29.2,36.99) 29.2,36.83 arc(29.29,36.63) 29.49,36.54 29.78,36.54 arc(29.91,36.6) 29.97,36.74 29.97,36.89 arc(29.95,36.93) 29.91,36.95 arc(29.86,36.97) 29.84,37.01 29.84,37.19 arc(29.86,37.24) 29.91,37.26 arc(29.95,37.27) 29.97,37.32 29.97,37.5 arc(29.95,37.54) 29.91,37.56 arc(29.86,37.58) 29.84,37.62 29.84,37.8 arc(29.86,37.85) 29.91,37.87 arc(29.95,37.88) 29.97,37.93 29.97,38.11 arc(29.95,38.15) 29.91,38.17 arc(29.86,38.19) 29.84,38.23 29.84,38.41 arc(29.86,38.46) 29.91,38.47 arc(29.95,38.49) 29.97,38.54 29.97,38.96 arc(29.88,39.18) 29.66,39.27 29.44,39.27 arc(29.39,39.25) 29.37,39.2 arc(29.35,39.16) 29.31,39.14 29.13,39.14 arc(29.09,39.16) 29.07,39.2 arc(29.05,39.25) 29.01,39.27 28.83,39.27 arc(28.78,39.25) 28.76,39.2 arc(28.75,39.16) 28.7,39.14 28.52,39.14 arc(28.48,39.16) 28.46,39.2 arc(28.44,39.25) 28.4,39.27 28.19,39.27 arc(28.14,39.25) 28.12,39.19 arc(28.09,39.14) 28.04,39.12 27.81,39.12 arc(27.76,39.14) 27.74,39.19 arc(27.71,39.25) 27.66,39.27 26.91,39.27 arc(26.74,39.24) 26.6,39.14 26.39,38.93 arc(26.22,38.68) 26.16,38.38 26.16,37.57 arc(25.8,35.73) 24.76,34.17 23.75,33.17 arc(22.91,32.61) 21.92,32.41 17.87,32.41 arc(17.36,32.31) 16.94,32.02 14.46,29.55 arc(14.17,29.12) 14.07,28.61 14.07,24.89 arc(13.87,24.41) 13.39,24.21 12.43,24.21 arc(11.93,24.11) 11.5,23.82 10.31,22.63 arc(9.78,21.84) 9.6,20.92 9.6,18.05 arc(9.56,17.85) 9.45,17.68 9.13,17.36 arc(9.08,17.28) 9.05,17.17 9.05,16.97 arc(9.13,16.78) 9.32,16.7 arc(9.51,16.74) 9.67,16.85 v1(9.83,17)
MIPI_DPHY_CSI0_RX_CLKP: length 100.1
  TOP w0.084: J14.9 7.26,16.35 arc(7.35,16.37) 7.42,16.42 7.44,16.43 arc(7.51,16.48) 7.6,16.5 9.32,16.5 arc(9.51,16.46) 9.67,16.35 v1(9.83,16.2) ; CN3.13 78.32,45.48 arc(78.31,45.42) 78.28,45.37 78.27,45.36 arc(78.23,45.31) 78.22,45.25 78.22,44.07 arc(78.09,43.43) 77.73,42.88 73.41,38.57 arc(72.87,38.2) 72.23,38.07 34.65,38.07 arc(34.25,37.99) 33.91,37.77 33.84,37.7 arc(33.44,37.43) 32.96,37.34 32.84,37.34 arc(32.42,37.25) 32.06,37.01 31.93,36.89 arc(31.44,36.56) 30.87,36.44 29.78,36.44 arc(29.57,36.4) 29.38,36.28 v1(29.2,36.1)
  ART03 w0.076: v1(29.2,36.1) 29.33,36.22 arc(29.45,36.31) 29.6,36.34 29.78,36.34 arc(30.06,36.45) 30.18,36.74 30.18,38.96 arc(30.02,39.32) 29.66,39.47 26.91,39.47 arc(26.66,39.42) 26.46,39.29 26.24,39.07 arc(26.03,38.76) 25.96,38.38 25.96,37.57 arc(25.61,35.81) 24.61,34.32 23.61,33.31 arc(22.84,32.8) 21.92,32.61 17.87,32.61 arc(17.29,32.5) 16.79,32.17 14.31,29.69 arc(13.98,29.2) 13.87,28.61 13.87,24.89 arc(13.73,24.55) 13.39,24.41 12.43,24.41 arc(11.85,24.29) 11.36,23.96 10.16,22.77 arc(9.6,21.92) 9.4,20.92 9.4,18.34 9.4,18.05 arc(9.37,17.93) 9.31,17.82 8.99,17.51 arc(8.89,17.35) 8.85,17.17 8.85,16.97 arc(8.99,16.64) 9.32,16.5 arc(9.51,16.46) 9.67,16.35 v1(9.83,16.2)
MIPI_DPHY_CSI0_RX_D0N: length 106.6
  TOP w0.084: CN3.3 76.32,45.48 arc(76.33,45.42) 76.37,45.37 76.38,45.36 arc(76.41,45.31) 76.42,45.25 76.42,44.82 arc(76.34,44.38) 76.09,44.01 71.94,39.86 arc(71.82,39.78) 71.68,39.75 61.1,39.75 arc(60.95,39.78) 60.82,39.87 60.74,39.94 arc(60.54,40.08) 60.3,40.13 59.59,40.13 arc(59.35,40.08) 59.14,39.94 59.07,39.87 arc(58.82,39.7) 58.53,39.64 30.46,39.64 arc(29.96,39.54) 29.53,39.26 28.64,38.37 arc(28.52,38.29) 28.37,38.26 28.11,38.26 arc(27.96,38.29) 27.83,38.37 v1(27.6,38.6) ; v1(10.85,18.33) 10.67,18.16 arc(10.54,18.07) 10.38,18.04 8.7,18.04 arc(8.48,17.99) 8.29,17.87 8.23,17.81 arc(8.11,17.73) 7.96,17.7 7.6,17.7 arc(7.51,17.72) 7.43,17.77 7.42,17.78 arc(7.35,17.83) 7.26,17.85 J14.12
  ART03 w0.076: v1(10.85,18.33) 10.85,18.23 arc(10.83,18.14) 10.78,18.07 10.72,18.01 arc(10.64,17.95) 10.54,17.93 10.42,17.93 10.36,17.99 arc(10.32,18.05) 10.31,18.11 10.31,20.81 arc(10.41,21.31) 10.7,21.74 11.2,22.24 arc(11.63,22.53) 12.14,22.63 14.5,22.63 arc(14.74,22.73) 14.83,22.96 14.83,23.29 arc(14.89,23.43) 15.02,23.48 16.09,23.48 arc(16.48,23.88) 16.09,24.27 15.1,24.27 arc(14.91,24.35) 14.83,24.54 14.83,24.66 arc(14.88,24.78) 15,24.83 16.12,24.83 arc(16.51,25.22) 16.12,25.61 15.02,25.61 arc(14.83,25.8) 15.02,25.99 16.12,25.99 arc(16.51,26.39) 16.12,26.78 15.02,26.78 arc(14.83,26.97) 15.02,27.16 16.12,27.16 arc(16.51,27.56) 16.12,27.95 15.03,27.95 arc(14.89,28.01) 14.83,28.15 14.83,28.17 arc(14.87,28.35) 14.97,28.5 17.66,31.19 arc(18.08,31.47) 18.59,31.57 21.62,31.57 arc(23.17,31.88) 24.49,32.76 25.62,33.89 arc(26.03,34.17) 26.52,34.26 27.16,34.26 arc(27.58,34.35) 27.94,34.59 28.13,34.78 arc(28.46,35.27) 28.57,35.85 28.57,35.88 arc(28.39,36.33) 27.94,36.52 27.34,36.52 arc(27.15,36.71) 27.34,36.9 28.18,36.9 arc(28.46,37.02) 28.57,37.29 28.57,37.79 arc(28.47,38.05) 28.2,38.16 27.74,38.16 arc(27.66,38.17) 27.59,38.22 27.56,38.25 arc(27.5,38.41) 27.56,38.56 v1(27.6,38.6)
MIPI_DPHY_CSI0_RX_D0P: length 106.4
  TOP w0.084: CN3.5 76.72,45.48 arc(76.71,45.42) 76.68,45.37 76.67,45.36 arc(76.63,45.31) 76.62,45.25 76.62,44.82 arc(76.52,44.3) 76.23,43.87 72.08,39.72 arc(71.89,39.6) 71.68,39.55 61.1,39.55 arc(60.87,39.6) 60.68,39.73 60.6,39.8 arc(60.46,39.9) 60.3,39.93 59.59,39.93 arc(59.42,39.9) 59.28,39.8 59.21,39.73 arc(58.9,39.52) 58.53,39.45 30.46,39.45 arc(30.03,39.36) 29.67,39.12 28.78,38.23 arc(28.59,38.1) 28.37,38.06 28.11,38.06 arc(27.96,38.03) 27.83,37.94 v1(27.6,37.71) ; v1(10.85,17.44) 10.85,17.5 10.67,17.68 arc(10.49,17.8) 10.28,17.84 8.7,17.84 arc(8.56,17.81) 8.43,17.73 8.37,17.67 arc(8.19,17.54) 7.96,17.5 7.6,17.5 arc(7.51,17.48) 7.44,17.43 7.42,17.42 arc(7.35,17.37) 7.26,17.35 J14.11
  ART03 w0.076: v1(27.6,37.71) 27.73,37.84 arc(27.85,37.92) 28,37.95 28.2,37.95 arc(28.32,37.91) 28.37,37.79 28.37,37.29 arc(28.32,37.16) 28.18,37.1 27.34,37.1 arc(26.95,36.71) 27.34,36.32 27.94,36.32 arc(28.24,36.19) 28.37,35.88 28.37,35.85 arc(28.27,35.35) 27.98,34.92 27.8,34.73 arc(27.5,34.54) 27.16,34.47 26.52,34.47 arc(25.95,34.36) 25.48,34.04 24.35,32.91 arc(23.09,32.07) 21.62,31.78 18.59,31.78 arc(18.01,31.66) 17.51,31.33 14.83,28.65 arc(14.68,28.43) 14.63,28.17 14.63,28.15 arc(14.75,27.86) 15.03,27.75 16.12,27.75 arc(16.31,27.56) 16.12,27.37 15.02,27.37 arc(14.63,26.97) 15.02,26.58 16.12,26.58 arc(16.31,26.39) 16.12,26.2 15.02,26.2 arc(14.63,25.8) 15.02,25.41 16.12,25.41 arc(16.31,25.22) 16.12,25.03 15,25.03 arc(14.74,24.92) 14.63,24.66 14.63,24.54 arc(14.77,24.2) 15.1,24.07 16.09,24.07 arc(16.28,23.88) 16.09,23.69 15.02,23.69 arc(14.75,23.57) 14.63,23.29 14.63,22.96 arc(14.59,22.87) 14.5,22.83 12.14,22.83 arc(11.55,22.72) 11.06,22.39 10.56,21.88 arc(10.23,21.39) 10.11,20.81 10.11,18.11 arc(10.14,17.97) 10.22,17.85 10.34,17.73 10.46,17.73 arc(10.55,17.71) 10.63,17.66 v1(10.85,17.44)
MIPI_DPHY_CSI0_RX_D1N: length 107.4
  TOP w0.084: v1(30.94,38.33) 30.94,38.05 arc(30.99,37.93) 31.1,37.88 31.35,37.88 arc(31.41,37.89) 31.47,37.93 32.01,38.47 arc(32.55,38.83) 33.19,38.96 71.62,38.96 arc(72.19,39.07) 72.67,39.39 76.79,43.52 arc(77.11,44) 77.22,44.56 77.22,45.25 arc(77.21,45.31) 77.18,45.36 77.17,45.37 arc(77.13,45.42) 77.12,45.48 CN3.7 ; J14.8 7.26,15.85 arc(7.35,15.83) 7.42,15.78 7.43,15.77 arc(7.51,15.72) 7.6,15.7 10.6,15.7 arc(10.71,15.72) 10.8,15.78 10.9,15.87 v1(10.9,15.94)
  ART03 w0.076: v1(30.94,38.33) 30.89,38.28 arc(30.84,38.16) 30.89,38.05 30.93,38.01 arc(31.08,37.9) 31.27,37.87 31.4,37.87 arc(31.59,37.95) 31.67,38.14 31.67,38.91 arc(31.66,38.96) 31.63,39 31.53,39.11 arc(31.48,39.13) 31.43,39.11 arc(31.38,39.09) 31.33,39.11 31.21,39.22 arc(31.19,39.27) 31.21,39.32 arc(31.23,39.37) 31.21,39.42 31.1,39.54 arc(31.05,39.56) 31,39.54 31,39.54 arc(30.95,39.52) 30.9,39.54 30.78,39.65 arc(30.76,39.7) 30.78,39.75 30.78,39.76 arc(30.8,39.81) 30.78,39.86 30.67,39.97 arc(30.62,39.99) 30.57,39.97 arc(30.51,39.95) 30.46,39.97 30.35,40.08 arc(30.33,40.14) 30.35,40.19 arc(30.37,40.24) 30.35,40.29 30.23,40.41 arc(30.17,40.45) 30.1,40.46 29.93,40.46 arc(29.89,40.44) 29.87,40.4 arc(29.85,40.35) 29.8,40.34 29.63,40.34 arc(29.58,40.35) 29.56,40.4 arc(29.54,40.44) 29.5,40.46 29.32,40.46 arc(29.28,40.44) 29.26,40.4 arc(29.24,40.35) 29.2,40.34 29.02,40.34 arc(28.97,40.35) 28.95,40.4 arc(28.94,40.44) 28.89,40.46 28.71,40.46 arc(28.67,40.44) 28.65,40.4 arc(28.63,40.35) 28.59,40.34 28.41,40.34 arc(28.36,40.35) 28.34,40.4 arc(28.33,40.44) 28.28,40.46 28.1,40.46 arc(28.06,40.44) 28.04,40.4 arc(28.02,40.35) 27.98,40.34 27.8,40.34 arc(27.75,40.35) 27.73,40.4 arc(27.72,40.44) 27.67,40.46 27.06,40.46 arc(26.58,40.37) 26.18,40.1 25.61,39.53 arc(25.32,39.1) 25.22,38.59 25.22,38.18 arc(24.76,35.87) 23.46,33.91 23.28,33.74 arc(22.77,33.39) 22.16,33.27 17.62,33.27 arc(17.12,33.17) 16.69,32.89 12.91,29.11 arc(12.79,28.93) 12.75,28.72 12.75,28.58 arc(12.63,28.29) 12.35,28.18 11.64,28.18 arc(11.45,27.99) 11.64,27.8 12.18,27.8 arc(12.58,27.63) 12.75,27.22 12.75,27.19 arc(12.58,26.78) 12.16,26.61 11.95,26.61 arc(11.76,26.42) 11.95,26.23 12.33,26.23 arc(12.7,26.07) 12.85,25.71 12.85,25.69 arc(12.7,25.32) 12.33,25.17 10.5,25.17 arc(10,25.07) 9.57,24.78 8.95,24.16 arc(8.66,23.73) 8.56,23.23 8.56,18.16 arc(8.52,17.94) 8.39,17.75 8.27,17.63 arc(8.15,17.45) 8.1,17.23 8.1,16.54 arc(8.17,16.18) 8.37,15.88 8.39,15.87 arc(8.68,15.67) 9.04,15.6 10.32,15.6 arc(10.54,15.65) 10.72,15.77 v1(10.9,15.94)
MIPI_DPHY_CSI0_RX_D1P: length 107.3
  TOP w0.084: J14.7 7.26,15.35 arc(7.35,15.37) 7.42,15.42 7.44,15.43 arc(7.51,15.48) 7.6,15.5 10.28,15.5 arc(10.44,15.47) 10.57,15.38 v1(10.9,15.06) ; CN3.9 77.52,45.48 arc(77.51,45.42) 77.48,45.37 77.47,45.36 arc(77.43,45.31) 77.42,45.25 77.42,44.56 arc(77.29,43.92) 76.93,43.38 72.81,39.25 arc(72.26,38.89) 71.62,38.76 33.19,38.76 arc(32.63,38.65) 32.15,38.33 31.61,37.79 arc(31.49,37.71) 31.35,37.68 31.33,37.68 arc(31.19,37.65) 31.07,37.58 v1(30.94,37.44)
  ART03 w0.076: v1(10.9,15.06) 10.66,15.29 arc(10.54,15.37) 10.4,15.4 9.04,15.4 arc(8.61,15.48) 8.24,15.73 8.23,15.74 arc(7.98,16.11) 7.9,16.54 7.9,17.23 arc(7.96,17.53) 8.12,17.78 8.25,17.9 arc(8.33,18.02) 8.36,18.16 8.36,23.23 arc(8.47,23.81) 8.8,24.31 9.43,24.93 arc(9.92,25.26) 10.5,25.37 12.33,25.37 arc(12.56,25.47) 12.65,25.69 12.65,25.71 arc(12.56,25.93) 12.33,26.02 11.95,26.02 arc(11.56,26.42) 11.95,26.81 12.16,26.81 arc(12.44,26.92) 12.55,27.19 12.55,27.22 arc(12.44,27.49) 12.18,27.59 11.64,27.59 arc(11.25,27.99) 11.64,28.38 12.35,28.38 arc(12.49,28.44) 12.55,28.58 12.55,28.72 arc(12.6,29.01) 12.77,29.25 16.55,33.03 arc(17.04,33.36) 17.62,33.48 22.16,33.48 arc(22.69,33.58) 23.14,33.88 23.31,34.06 arc(24.58,35.95) 25.02,38.18 25.02,38.59 arc(25.14,39.18) 25.47,39.67 26.03,40.24 arc(26.5,40.55) 27.06,40.67 30.1,40.67 arc(30.25,40.64) 30.37,40.55 31.78,39.15 arc(31.85,39.04) 31.88,38.91 31.88,38.14 arc(31.74,37.8) 31.4,37.66 31.32,37.66 arc(31.18,37.64) 31.06,37.56 v1(30.94,37.44)
MIPI_DPHY_CSI0_RX_D2N: length 100
  TOP w0.084: J14.17 7.26,20.35 arc(7.35,20.33) 7.42,20.28 7.43,20.27 arc(7.51,20.22) 7.6,20.2 10.43,20.2 arc(10.59,20.23) 10.71,20.31 10.81,20.41 arc(10.83,20.44) 10.84,20.48 v1(10.84,20.53) ; CN3.15 78.72,45.48 arc(78.73,45.42) 78.77,45.37 78.78,45.36 arc(78.81,45.31) 78.82,45.25 78.82,43.62 arc(78.71,43.06) 78.39,42.58 73.86,38.05 arc(73.38,37.72) 72.81,37.61 36.12,37.61 arc(35.48,37.48) 34.94,37.12 34.22,36.41 arc(33.98,36.24) 33.69,36.19 33.59,36.19 arc(33.38,36.23) 33.19,36.35 v1(33.01,36.53)
  ART03 w0.076: v1(10.84,20.53) 11.01,20.36 arc(11.19,20.24) 11.39,20.2 11.62,20.2 arc(11.99,20.05) 12.14,19.69 12.14,19.37 arc(12.33,19.18) 12.52,19.37 12.52,19.78 arc(12.63,20.06) 12.91,20.18 13.02,20.18 arc(13.37,20.03) 13.51,19.69 13.51,19.04 arc(13.7,18.85) 13.89,19.04 13.89,19.78 arc(14,20.06) 14.28,20.18 14.39,20.18 arc(14.74,20.03) 14.88,19.69 14.88,19.44 arc(15.07,19.25) 15.26,19.44 15.26,19.78 arc(15.65,20.18) 16.05,19.78 16.05,19.42 arc(16.1,19.3) 16.22,19.25 17.66,19.25 arc(17.75,19.27) 17.82,19.32 17.84,19.34 arc(17.89,19.41) 17.91,19.5 17.91,19.61 arc(17.85,19.74) 17.72,19.8 17.03,19.8 arc(16.64,20.19) 17.03,20.59 17.72,20.59 arc(17.85,20.64) 17.91,20.78 17.91,29.07 arc(17.95,29.27) 18.06,29.44 18.67,30.05 arc(18.84,30.16) 19.04,30.2 25.44,30.2 arc(26.67,30.44) 27.71,31.14 29.08,32.51 arc(29.56,32.83) 30.12,32.94 30.83,32.94 arc(31.04,32.99) 31.22,33.11 31.23,33.12 arc(31.35,33.3) 31.39,33.51 31.39,34.89 arc(31.48,35.35) 31.74,35.73 31.84,35.83 arc(32.13,36.02) 32.47,36.09 32.76,36.09 arc(32.85,36.11) 32.93,36.16 32.94,36.17 arc(32.99,36.25) 33.01,36.34 v1(33.01,36.53)
MIPI_DPHY_CSI0_RX_D2P: length 100.1
  TOP w0.084: J14.16 7.26,19.85 arc(7.35,19.87) 7.42,19.92 7.43,19.93 arc(7.51,19.98) 7.6,20 10.31,20 arc(10.47,19.97) 10.6,19.88 v1(10.84,19.64) ; CN3.17 79.12,45.48 arc(79.11,45.42) 79.08,45.37 79.07,45.36 arc(79.03,45.31) 79.02,45.25 79.02,43.62 arc(78.89,42.98) 78.53,42.44 74,37.91 arc(73.46,37.54) 72.81,37.41 36.12,37.41 arc(35.56,37.3) 35.08,36.98 34.36,36.27 arc(34.05,36.06) 33.69,35.99 33.59,35.99 arc(33.38,35.94) 33.19,35.82 v1(33.01,35.64)
  ART03 w0.076: v1(33.01,35.64) 32.89,35.77 arc(32.76,35.85) 32.61,35.88 32.47,35.88 arc(32.2,35.83) 31.98,35.68 31.88,35.58 arc(31.67,35.27) 31.6,34.89 31.6,33.51 arc(31.54,33.22) 31.38,32.98 31.36,32.96 arc(31.12,32.8) 30.83,32.74 30.12,32.74 arc(29.64,32.64) 29.23,32.37 27.86,31 arc(26.75,30.26) 25.44,30 19.04,30 arc(18.92,29.97) 18.81,29.9 18.21,29.3 arc(18.13,29.19) 18.11,29.07 18.11,20.78 arc(17.99,20.5) 17.72,20.38 17.03,20.38 arc(16.84,20.19) 17.03,20 17.72,20 arc(17.99,19.89) 18.11,19.61 18.11,19.5 arc(18.08,19.34) 17.98,19.19 17.97,19.18 arc(17.83,19.08) 17.66,19.05 16.22,19.05 arc(15.95,19.16) 15.84,19.42 15.84,19.78 arc(15.65,19.97) 15.46,19.78 15.46,19.44 arc(15.07,19.05) 14.68,19.44 14.68,19.69 arc(14.59,19.89) 14.39,19.97 14.28,19.97 arc(14.15,19.92) 14.09,19.78 14.09,19.04 arc(13.7,18.64) 13.3,19.04 13.3,19.69 arc(13.22,19.89) 13.02,19.97 12.91,19.97 arc(12.78,19.92) 12.72,19.78 12.72,19.37 arc(12.33,18.97) 11.93,19.37 11.93,19.69 arc(11.84,19.91) 11.62,20 11.44,20 arc(11.21,19.95) 11.02,19.83 v1(10.84,19.64)
MIPI_DPHY_CSI0_RX_D3N: length 95.8
  TOP w0.084: v1(30.93,35.26) 31.11,35.08 arc(31.3,34.96) 31.51,34.92 33.72,34.92 arc(34.07,34.99) 34.37,35.19 35.83,36.64 arc(36.21,36.89) 36.65,36.98 72.94,36.98 arc(73.82,37.16) 74.55,37.65 78.88,41.97 arc(79.31,42.61) 79.46,43.37 79.46,44.76 79.62,44.93 79.62,45.25 arc(79.61,45.31) 79.58,45.36 79.57,45.37 arc(79.53,45.42) 79.52,45.48 CN3.19 ; J14.20 7.26,21.85 arc(7.35,21.83) 7.42,21.78 7.43,21.77 arc(7.51,21.72) 7.6,21.7 11.37,21.7 arc(11.55,21.74) 11.71,21.84 v1(11.86,21.99)
  ART03 w0.076: v1(11.86,21.99) 11.87,21.99 12.07,21.79 arc(12.29,21.65) 12.54,21.6 13.93,21.6 arc(14.2,21.48) 14.32,21.21 14.32,20.99 arc(14.51,20.8) 14.7,20.99 14.7,21.21 arc(15.09,21.6) 15.49,21.21 15.49,20.99 arc(15.68,20.8) 15.87,20.99 15.87,21.21 arc(15.98,21.48) 16.26,21.6 16.57,21.6 arc(16.74,21.67) 16.81,21.84 16.81,21.84 arc(16.77,21.95) 16.66,22 15.81,22 arc(15.42,22.39) 15.81,22.78 16.91,22.78 arc(17.07,22.85) 17.14,23.02 17.14,29.07 arc(17.26,29.65) 17.59,30.15 17.99,30.54 arc(18.48,30.87) 19.06,30.99 21.92,30.99 arc(23.21,31.24) 24.31,31.98 24.43,32.11 arc(24.93,32.31) 25.43,32.11 25.94,31.59 arc(26.55,31.34) 27.16,31.59 28,32.43 arc(28.07,32.53) 28.09,32.65 28.09,32.94 arc(28.19,33.42) 28.46,33.82 29,34.37 arc(29.5,34.7) 30.08,34.82 30.83,34.82 arc(30.94,34.86) 30.99,34.98 30.99,35.21 v1(30.93,35.26)
MIPI_DPHY_CSI0_RX_D3P: length 95.7
  TOP w0.084: J14.19 7.26,21.35 arc(7.35,21.37) 7.42,21.42 7.44,21.43 arc(7.51,21.48) 7.6,21.5 11.19,21.5 arc(11.45,21.45) 11.66,21.31 11.86,21.1 v1(11.87,21.1) ; v1(30.93,34.37) 31.11,34.55 arc(31.3,34.67) 31.51,34.72 33.72,34.72 arc(34.15,34.8) 34.51,35.05 35.97,36.5 arc(36.28,36.71) 36.65,36.78 72.94,36.78 arc(73.89,36.97) 74.69,37.51 79.02,41.83 arc(79.49,42.54) 79.65,43.37 79.65,44.68 79.82,44.85 79.82,45.25 arc(79.83,45.31) 79.87,45.36 79.88,45.37 arc(79.91,45.42) 79.92,45.48 CN3.21
  ART03 w0.076: v1(11.87,21.1) 12.02,21.26 arc(12.18,21.36) 12.36,21.4 13.93,21.4 arc(14.06,21.34) 14.12,21.21 14.12,20.99 arc(14.51,20.6) 14.9,20.99 14.9,21.21 arc(15.09,21.4) 15.29,21.21 15.29,20.99 arc(15.68,20.6) 16.07,20.99 16.07,21.21 arc(16.13,21.34) 16.26,21.4 16.57,21.4 arc(16.88,21.52) 17.02,21.83 arc(16.92,22.09) 16.66,22.2 15.81,22.2 arc(15.62,22.39) 15.81,22.58 16.91,22.58 arc(17.22,22.71) 17.35,23.02 17.35,29.07 arc(17.45,29.57) 17.74,30 18.13,30.4 arc(18.56,30.68) 19.06,30.78 21.92,30.78 arc(23.29,31.06) 24.45,31.83 24.58,31.96 arc(24.93,32.11) 25.28,31.96 25.8,31.45 arc(26.55,31.13) 27.3,31.45 28.15,32.29 arc(28.26,32.45) 28.3,32.65 28.3,32.94 arc(28.37,33.34) 28.6,33.68 29.15,34.23 arc(29.58,34.51) 30.08,34.61 30.53,34.61 arc(30.68,34.58) 30.81,34.5 v1(30.93,34.37)
MIPI_DPHY_CSI1_RX_CLKN: length 73.6
  TOP w0.084: v1(64.92,51.79) 64.92,51.6 arc(64.89,51.45) 64.8,51.32 64.63,51.15 arc(64.48,50.91) 64.42,50.64 64.42,49.65 arc(64.41,49.59) 64.38,49.54 64.37,49.53 arc(64.33,49.48) 64.32,49.42 CN2.62 ; v1(13.26,44.18) 13.13,44.05 arc(13,43.96) 12.85,43.93 12.12,43.93 arc(11.43,43.8) 10.84,43.41 9.7,42.26 arc(9.31,41.68) 9.17,40.99 9.17,40.21 arc(9.09,39.81) 8.87,39.47 8.8,39.41 arc(8.53,39.01) 8.44,38.53 8.44,36.84 arc(8.37,36.48) 8.17,36.18 7.98,36 arc(7.87,35.93) 7.74,35.9 7.6,35.9 arc(7.51,35.92) 7.43,35.97 7.42,35.98 arc(7.35,36.03) 7.26,36.05 J15.10
  BOTTOM w0.084: v1(64.92,51.79) 64.92,51.63 arc(64.9,51.5) 64.82,51.39 64.65,51.21 arc(64.49,50.98) 64.44,50.7 64.44,50.17 arc(64.43,50.12) 64.39,50.07 63.42,49.1 arc(62.94,48.78) 62.38,48.67 53.45,48.67 arc(52.81,48.54) 52.26,48.18 46.63,42.54 arc(46.15,42.22) 45.59,42.11 41.99,42.11 arc(41.43,42.22) 40.95,42.54 40.88,42.61 arc(40.34,42.97) 39.7,43.1 36.81,43.1 arc(36.17,42.97) 35.62,42.61 35.07,42.06 arc(34.59,41.74) 34.03,41.63 19.39,41.63 arc(18.82,41.74) 18.34,42.06 17.47,42.94 arc(17.14,43.15) 16.76,43.23 14.59,43.23 arc(14.53,43.24) 14.49,43.27 13.83,43.93 13.66,43.93 arc(13.51,43.96) 13.38,44.05 13.26,44.17 v1(13.26,44.18)
MIPI_DPHY_CSI1_RX_CLKP: length 73.7
  TOP w0.084: v1(13.26,43.29) 13.29,43.32 arc(13.35,43.46) 13.29,43.6 arc(13.15,43.7) 12.98,43.73 12.12,43.73 arc(11.5,43.61) 10.98,43.27 9.84,42.12 arc(9.49,41.6) 9.37,40.99 9.37,40.21 arc(9.27,39.73) 9.01,39.33 8.94,39.27 arc(8.72,38.93) 8.64,38.53 8.64,36.84 arc(8.55,36.41) 8.31,36.04 8.12,35.86 arc(7.95,35.74) 7.74,35.7 7.6,35.7 arc(7.51,35.68) 7.44,35.63 7.42,35.62 arc(7.35,35.57) 7.26,35.55 J15.9 ; v1(64.92,50.79) 64.78,50.79 arc(64.67,50.74) 64.62,50.63 64.62,49.65 arc(64.63,49.59) 64.67,49.54 64.68,49.53 arc(64.71,49.48) 64.72,49.42 CN2.64
  BOTTOM w0.084: v1(13.26,43.29) 13.23,43.32 arc(13.19,43.37) 13.18,43.43 13.18,43.56 arc(13.23,43.68) 13.36,43.73 13.75,43.73 13.92,43.56 arc(13.95,43.49) 13.92,43.42 13.92,43.42 arc(13.89,43.35) 13.92,43.28 14.02,43.18 arc(14.09,43.15) 14.16,43.18 arc(14.23,43.21) 14.3,43.18 14.45,43.03 14.66,43.03 arc(14.71,43.01) 14.72,42.97 arc(14.74,42.92) 14.79,42.9 14.99,42.9 arc(15.04,42.92) 15.06,42.97 arc(15.08,43.01) 15.13,43.03 15.33,43.03 arc(15.38,43.01) 15.39,42.97 arc(15.41,42.92) 15.46,42.9 15.66,42.9 arc(15.71,42.92) 15.73,42.97 arc(15.75,43.01) 15.8,43.03 16,43.03 arc(16.05,43.01) 16.07,42.97 arc(16.08,42.92) 16.13,42.9 16.33,42.9 arc(16.38,42.92) 16.4,42.97 arc(16.42,43.01) 16.47,43.03 16.76,43.03 arc(17.06,42.97) 17.33,42.8 18.2,41.92 arc(18.75,41.55) 19.39,41.43 34.03,41.43 arc(34.67,41.55) 35.21,41.92 35.76,42.47 arc(36.24,42.79) 36.81,42.9 39.7,42.9 arc(40.26,42.79) 40.74,42.47 40.81,42.4 arc(41.35,42.04) 41.99,41.91 45.59,41.91 arc(46.23,42.04) 46.77,42.4 52.4,48.04 arc(52.88,48.36) 53.45,48.47 62.38,48.47 arc(63.02,48.6) 63.56,48.96 64.13,49.52 arc(64.19,49.55) 64.24,49.52 arc(64.3,49.5) 64.36,49.52 64.48,49.65 arc(64.5,49.7) 64.48,49.76 arc(64.46,49.82) 64.48,49.88 64.63,50.03 64.63,50.69 64.73,50.79 v1(64.92,50.79)
